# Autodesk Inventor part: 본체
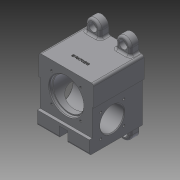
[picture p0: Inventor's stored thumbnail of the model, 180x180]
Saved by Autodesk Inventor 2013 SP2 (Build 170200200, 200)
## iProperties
Created: 2024-11
Part Number: 본체
Material: 알루미늄 6061
Document SubType Name: Modeling
Designer: a
Density: 2.71 g/cm^3
Mass: 806.268 g
Surface Area: 539.349 cm^2
Volume: 297.516 cm^3
Author: a
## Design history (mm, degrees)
sketch "스케치1"
  geometry: L1 (-38, -42.5)-(38, -42.5); L2 (38, -42.5)-(38, 42.5); L3 (38, 42.5)-(-38, 42.5); L4 (-38, 42.5)-(-38, -42.5); L5 (-38, -42.5)-(38, 42.5); L6 (38, -42.5)-(-38, 42.5); 1 further point
  constraints: 12 end point, 2 midpoint, 2 parallel, 1 horizontal, 1 perpendicular
  dimensions: "d0" = 76 distance of L3.end L2.end; "d1" = 85 distance of L2.end L1.end
extrude "돌출1" new body sketch "스케치1" distance "d2" = 74; taper "d3" = 0 deg
sketch "스케치2"
  geometry: L1 (-38, -42.5)-(-36, -42.5); L2 (-36, -42.5)-(-36, 13.5); L3 (-36, 13.5)-(-38, 13.5); L4 (-38, 13.5)-(-38, -42.5); L5 (38, -42.5)-(36, -42.5); L6 (36, -42.5)-(36, 13.5); L7 (36, 13.5)-(38, 13.5); L8 (38, 13.5)-(38, -42.5); 1 further point
  constraints: 16 end point, 4 parallel, 2 horizontal, 2 perpendicular
  dimensions: "d4" = 2 distance of L2.end L3.end; "d6" = 2 distance of L6.end L7.end (= d4); "d7" = 56 distance of L5.end L6.end; "d8" = 56 distance of L1.end L2.end (= d7)
extrude "돌출2" cut sketch "스케치2" stored distance "d9" = 74; taper "d10" = 0 deg
sketch "스케치3"
  geometry: L1 (-36, -42.5)-(36, -42.5) reference; L2 (-6, -42.5)-(6, -42.5); L3 (6, -42.5)-(6, -27.5); L4 (6, -27.5)-(-6, -27.5); L5 (-6, -27.5)-(-6, -42.5); L6 (0, -27.5)-(0, 0)
  constraints: 10 end point, 2 parallel, 1 horizontal, 1 midpoint, 1 perpendicular, 1 point on line, 1 vertical
  dimensions: "d11" = 12 distance of L3.end L4.end; "d13" = 15 distance of L2.end L3.end
extrude "돌출3" cut sketch "스케치3" stored distance "d14" = 74; taper "d15" = 0 deg
sketch "스케치4"
  geometry: L1 (0, 85)-(-4, 85); L2 (-4, 85)-(-4, 19); L3 (-4, 19)-(0, 19); L4 (0, 19)-(0, 85); L5 (-74, 85)-(0, 85) reference; L6 (0, 56)-(0, 85) reference; 1 further point
  constraints: 8 end point, 2 collinear, 2 parallel, 1 horizontal, 1 perpendicular
  dimensions: "d16" = 4 distance between parallel lines of L2 L4; "d18" = 66 distance between parallel lines of L3 L1
extrude "돌출4" cut sketch "스케치4" stored distance "d19" = 74; taper "d20" = 0 deg
sketch "스케치5"
  geometry: L1 (-38, 42.5)-(38, 42.5) reference; L2 (-6, -27.5)-(6, -27.5) reference; L3 (-31, 42.5)-(-31, 52.5); L4 (-11, 42.5)-(-11, 52.5); A1 r 10 centre (-21, 52.5) between (-11, 52.5) and (-31, 52.5); 1 further point
  constraints: 4 end point, 2 point on circle, 2 point on line, 2 tangent, 1 centre point, 1 parallel, 1 perpendicular
  dimensions: "d21" = 21 horizontal distance of point (0, 0) A1.centre; "d22" = 20 distance between parallel lines of L4 L3; "d23" = 10 distance of L3.start L3.end
extrude "돌출5" join sketch "스케치5" distance "d24" = 12; taper "d25" = 0 deg
sketch "스케치6"
  geometry: A1 r 10 centre (21, 52.5) between (31, 52.5) and (11, 52.5) reference; 2 further points
  constraints: 1 coincident
hole "구멍1" sketch "스케치6" at (21, 52.5) diameter "d26" = 6.6; stored, may be unused: countersink angle "d30" = 90 deg, drill point angle "d32" = 118 deg; dims "d27" = 6, "d28" = 11, "d29" = 6.6, "d31" = 8
node "작업 평면1"
sketch "스케치7"
  geometry: L1 (-2, 66)-(74, 66) reference; L2 (72, 0)-(0, 0) reference; L3 (36, 23.5)-(36, 33); C1 r 23.5 at (36, 33)
  constraints: 2 end point, 1 centre point, 1 perpendicular
  dimensions: "d33" = 47 diameter of C1; "d34" = 33 distance from line of L3.end L1
extrude "돌출6" cut sketch "스케치7" distance "d35" = 4; taper "d36" = 0 deg
sketch "스케치8"
  geometry: C1 r 23.5 at (0, 0) reference; C2 r 22 at (0, 0); 1 further point
  constraints: 1 centre point, 1 coincident
  dimensions: "d37" = 44 diameter of C2
extrude "돌출7" cut sketch "스케치8" distance "d38" = 48; taper "d39" = 0 deg
sketch "스케치9"
  geometry: C1 r 22 at (0, 0) reference; C2 r 17.5 at (0, 0); 1 further point
  constraints: 1 centre point, 1 coincident
  dimensions: "d40" = 35 diameter of C2
extrude "돌출8" cut sketch "스케치9" distance "d41" = 11; taper "d42" = 0 deg
sketch "스케치10"
  geometry: C1 r 17.5 at (0, 0) reference; C2 r 15 at (0, 0); 1 further point
  constraints: 1 centre point, 1 coincident
  dimensions: "d43" = 30 diameter of C2
extrude "돌출9" cut sketch "스케치10" distance "d44" = 3; taper "d45" = 0 deg
chamfer "모따기1" distance "d46" = 1; stored, may be unused: second distance "d47" = 2, angle "d48" = 45 deg
fillet "모깎기1" dims "d49" = 3
chamfer "모따기2" distance "d50" = 1; stored, may be unused: second distance "d51" = 2, angle "d52" = 45 deg
fillet "모깎기3" dims "d54" = 3
sketch "스케치11"
  geometry: L1 (72, 0)-(0, 0) reference; L2 (36, 33)-(36, 61.5); L3 (36, 33)-(56.153, 53.153); C1 r 24.5 at (36, 33) reference; A1 r 28.5 centre (36, 33) between (36, 61.5) and (56.153, 53.153); 2 further points
  constraints: 4 end point, 2 coincident, 2 point on circle, 1 centre point, 1 perpendicular
  dimensions: "d55" = 57 diameter of A1; "d56" = 45 deg angle of L3 L2
hole "구멍2" sketch "스케치11" at (56.153, 53.153) diameter "d58" = 3.242; stored, may be unused: countersink angle "d62" = 90 deg, drill point angle "d64" = 118 deg; dims "d59" = 8, "d60" = 11, "d61" = 6.6, "d63" = 10
sketch "스케치12"
  geometry: L1 (-62.5, 0)-(-52.5, 0) reference; L2 (42.5, 0)-(42.5, 70) reference; C1 r 16.5 at (-14.5, 42); 1 further point
  constraints: 1 centre point
  dimensions: "d68" = 33 diameter of C1; "d69" = 42 distance from line of L1 C1.centre; "d70" = 57 distance from line of L2 C1.centre
extrude "돌출10" cut sketch "스케치12" stored distance "d71" = 3; taper "d72" = 0 deg
sketch "스케치13"
  geometry: L1 (-58, 12)-(-26, 12); L2 (-26, 12)-(-26, 44); L3 (-26, 44)-(-58, 44); L4 (-58, 44)-(-58, 12); L5 (-58, 12)-(-26, 44); L6 (-26, 12)-(-58, 44); C1 r 16.5 at (-42, 28) reference; 5 further points
  constraints: 12 end point, 4 coincident, 2 midpoint, 2 parallel, 1 horizontal, 1 perpendicular
  dimensions: "d73" = 32 distance of L1.start L1.end; "d75" = 32 distance of L1.end L2.end
hole "구멍3" sketch "스케치13" at (-58, 44), (-26, 44), (-26, 12), (-58, 12) diameter "d76" = 3.242; stored, may be unused: countersink angle "d80" = 90 deg, drill point angle "d82" = 118 deg; dims "d77" = 8, "d78" = 11, "d79" = 6.6, "d81" = 10
node "작업 평면2"
sketch "스케치14"
  geometry: L1 (0, 74)-(12, 74) reference; L2 (6, 74)-(6, 62); L3 (6, 62)-(6, 22); 2 further points
  constraints: 4 end point, 2 coincident, 1 collinear, 1 midpoint, 1 perpendicular
  dimensions: "d83" = 12 distance of L2.start L2.end; "d84" = 40 distance of L3.start L3.end
hole "구멍4" sketch "스케치14" at (6, 62), (6, 22) diameter "d85" = 3.242; stored, may be unused: countersink angle "d89" = 90 deg, drill point angle "d91" = 118 deg; dims "d86" = 8, "d87" = 11, "d88" = 6.6, "d90" = 10
sketch "스케치15"
  geometry: L1 (0, 0)-(76, 0) reference; L2 (38, 20)-(38, 0); 1 further point
  constraints: 2 end point, 1 midpoint, 1 vertical, 1 other
  dimensions: "d92" = 20 distance from line of L1 L2.start
feature "엠보싱1" sketch "스케치15" dims "d93" = 0.5, "d94" = 0
fillet "모깎기4" dims "d95" = 3
fillet "모깎기5" dims "d96" = 3
fillet "모깎기6" dims "d97" = 3
chamfer "모따기3" distance "d98" = 1; stored, may be unused: second distance "d99" = 2, angle "d100" = 45 deg
fillet "모깎기7" dims "d101" = 3
chamfer "모따기4" distance "d102" = 1; stored, may be unused: second distance "d103" = 2, angle "d104" = 45 deg
fillet "모깎기8" dims "d105" = 0.6
node "솔리드1"
mirror "대칭1"
mirror "대칭2"
pattern_circular "원형 패턴1" dims angle "d66" = 360 deg
mirror "대칭3"
